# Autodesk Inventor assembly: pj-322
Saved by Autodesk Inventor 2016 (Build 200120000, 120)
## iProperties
Created: 2018-05
Part Number: pj-322
Document SubType Name: Assembly
Designer: Administrator
Title: pj-322 v8
Author: Administrator
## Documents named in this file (6)
- c:\worker\convert-fusion-mar-2018\tmp\job-1\16\output\files\8c58ff39-88bb-4352-afd9-60265520bae5\pj-322 v8.iam
- c:\worker\convert-fusion-mar-2018\tmp\job-1\16\output\files\8c58ff39-88bb-4352-afd9-60265520bae5\tip_lead.ipt
- c:\worker\convert-fusion-mar-2018\tmp\job-1\16\output\files\8c58ff39-88bb-4352-afd9-60265520bae5\Component2_1.ipt
- c:\worker\convert-fusion-mar-2018\tmp\job-1\16\output\files\8c58ff39-88bb-4352-afd9-60265520bae5\Component3_1.ipt
- c:\worker\convert-fusion-mar-2018\tmp\job-1\16\output\files\8c58ff39-88bb-4352-afd9-60265520bae5\Component4_1.ipt
- c:\worker\convert-fusion-mar-2018\tmp\job-1\16\output\files\8c58ff39-88bb-4352-afd9-60265520bae5\pj-322 v8.ipt
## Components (5 placed, 5 different names)
1. tip_lead:1
2. Component2:1
3. Component3:1
4. Component4:1
5. pj-322 v8
